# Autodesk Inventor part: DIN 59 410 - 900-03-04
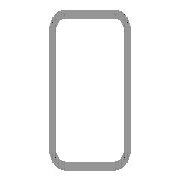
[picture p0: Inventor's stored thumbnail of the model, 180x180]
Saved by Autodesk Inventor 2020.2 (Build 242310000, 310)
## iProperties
Manager: www.cadconsulting.pl
Company: Fabian Stasiak CAD Consulting
Created: 2015-02
Part Number: DIN 59 410 - 900-03-04
Material: Stal, miękka
Description: Rurki stalowe o przekroju prostokątnym formowane na gorąco
Document SubType Name: Modellieren
Standard: DIN 59 410
Designer: F.Stasiak
Standards Organization: DIN
Language: pl-PL
Size Designation: 100x50x4.5-1680
Categories: <MemberInstance><Categories><Category DisplayName="Kształtowniki konstrukcyjne" InternalName="089c4875-fa83-4c05-b084-43b9cc11f5ed" Mnemonic="GRDR"><CategoryPar
Stock Number: 100x50x4.5
Density: 7.85 g/cm^3
Appearance: Częściowo polerowany
Mass: 21668.7 g
Surface Area: 11135.3 cm^2
Volume: 2760.34 cm^3
Catalog Web Link: www.expertbooks.pl
IsCustomPart: 1
G_L: 1800,000 mm
Author: F.Stasiak
Subject: Zbiór ćwiczeń. Autodesk Inventor 2020. Kurs Professional
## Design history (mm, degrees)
node "Płaszczyzna początkowa"
node "Płaszczyzna końcowa"
sketch "Szkic1"
  geometry: L1 (-20, 60)-(20, 60); L2 (30, 50)-(30, -50); L3 (20, -60)-(-20, -60); L4 (-30, -50)-(-30, 50); L5 (-44.61, 0)-(44.61, 0) reference; L6 (0, -86.61)-(0, 86.61) reference; L7 (-20, 55)-(20, 55); L8 (25, 50)-(25, -50); L9 (20, -55)-(-20, -55); L10 (-25, -50)-(-25, 50); A1 r 10 centre (-20, 50) between (-20, 60) and (-30, 50); A2 r 10 centre (20, 50) between (30, 50) and (20, 60); A3 r 10 centre (20, -50) between (20, -60) and (30, -50); A4 r 10 centre (-20, -50) between (-30, -50) and (-20, -60); A5 r 5 centre (-20, 50) between (-20, 55) and (-25, 50); A6 r 5 centre (20, 50) between (25, 50) and (20, 55); A7 r 5 centre (20, -50) between (20, -55) and (25, -50); A8 r 5 centre (-20, -50) between (-25, -50) and (-20, -55); 3 further points
  constraints: 16 end point, 16 point on circle, 8 centre point, 8 tangent, 6 point on line, 4 parallel, 3 equal radius, 2 perpendicular, 1 horizontal, 7 other
  dimensions: "b" = 60 distance of point (-30, 60) point (30, 60); "ParH" = 120 distance of point (30, 60) point (30, -60); "msp_r" = 10 radius of A1 (= 2 x ParT); "d8" = 30 distance between parallel lines of L4 L6 (= 0.5 x b); "d9" = 60 distance between parallel lines of L5 L1 (= 0.5 x ParH); "d10" = 5 distance between parallel lines of L4 L10 (= ParT)
extrude "Bryła" new body sketch "Szkic1" taper "d4" = 0 deg; stored distance "NLG" = 10
node "Driven Length"
  sketch "Sketch2"
    geometry: L1 (0, 0)-(10, 0) reference
    constraints: 2 end point, 1 horizontal
  workplane "Work Plane3"
  sketch "Sketch3"
    geometry: L1 (-2, 0)-(12, 0) reference; L2 (-2, 1800)-(12, 1800) reference
    dimensions: "d14" = 1800 distance between parallel lines of L1 L2 (derived)
sketch "Szkic4"
  geometry: L1 (0, 100)-(0, 0) reference; L2 (1800, 100)-(1800, 0) reference; L3 (0, 50)-(1800, 50); 3 further points
  constraints: 2 end point, 2 midpoint, 2 point on line, 1 horizontal
  dimensions: "d15" = 60 distance from line of L1 point (60, 50); "d16" = 60 distance from line of L2 point (1740, 50)
hole "Otwór1" sketch "Szkic4" at (900, 50), (1740, 50), (60, 50) diameter "d17" = 50; stored, may be unused: countersink angle "d21" = 90 deg, drill point angle "d23" = 118 deg; dims "d18" = 6, "d19" = 4, "d20" = 2, "d22" = 8
sketch "Szkic5"
  geometry: L1 (0, 10)-(1800, 10) reference; L2 (0, -110)-(1800, -110) reference; L3 (63.629, 10)-(10, -35); L4 (10, -35)-(10, -65); L5 (10, -65)-(63.629, -110); L6 (0, 10)-(0, -110); C1 r 25 at (60, -50) reference; 1 further point
  constraints: 8 end point, 2 point on line, 1 equal length, 1 perpendicular, 1 vertical, 1 vertical alignment
  dimensions: "d24" = 50 distance from line of C1.centre L4; "d25" = 130 deg angle of L3 L4; "d26" = 30 distance of L3.end L4.end
extrude "Wyciągnięcie proste2" cut sketch "Szkic5" extent not by distance; stored distance "d27" = 10; taper "d28" = 0 deg
node "Płaszczyzna konstrukcyjna5"
  node "Oś konstrukcyjna1"
mirror "Odbicie lustrzane1"
body "Solid1"
other parameters: "ParT" = 5, "G_OFFSET_START" = 0 [user parameter; used in 1 equation term], "G_OFFSET_END" = 0 [user parameter; used in 1 equation term], "d11" = 0 (computed from G_OFFSET_START), "G_L" = 1800 (= d14) [user parameter], "d13" = 90 deg, "d29" = 0
